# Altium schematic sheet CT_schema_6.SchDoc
size 308 x 321 mm
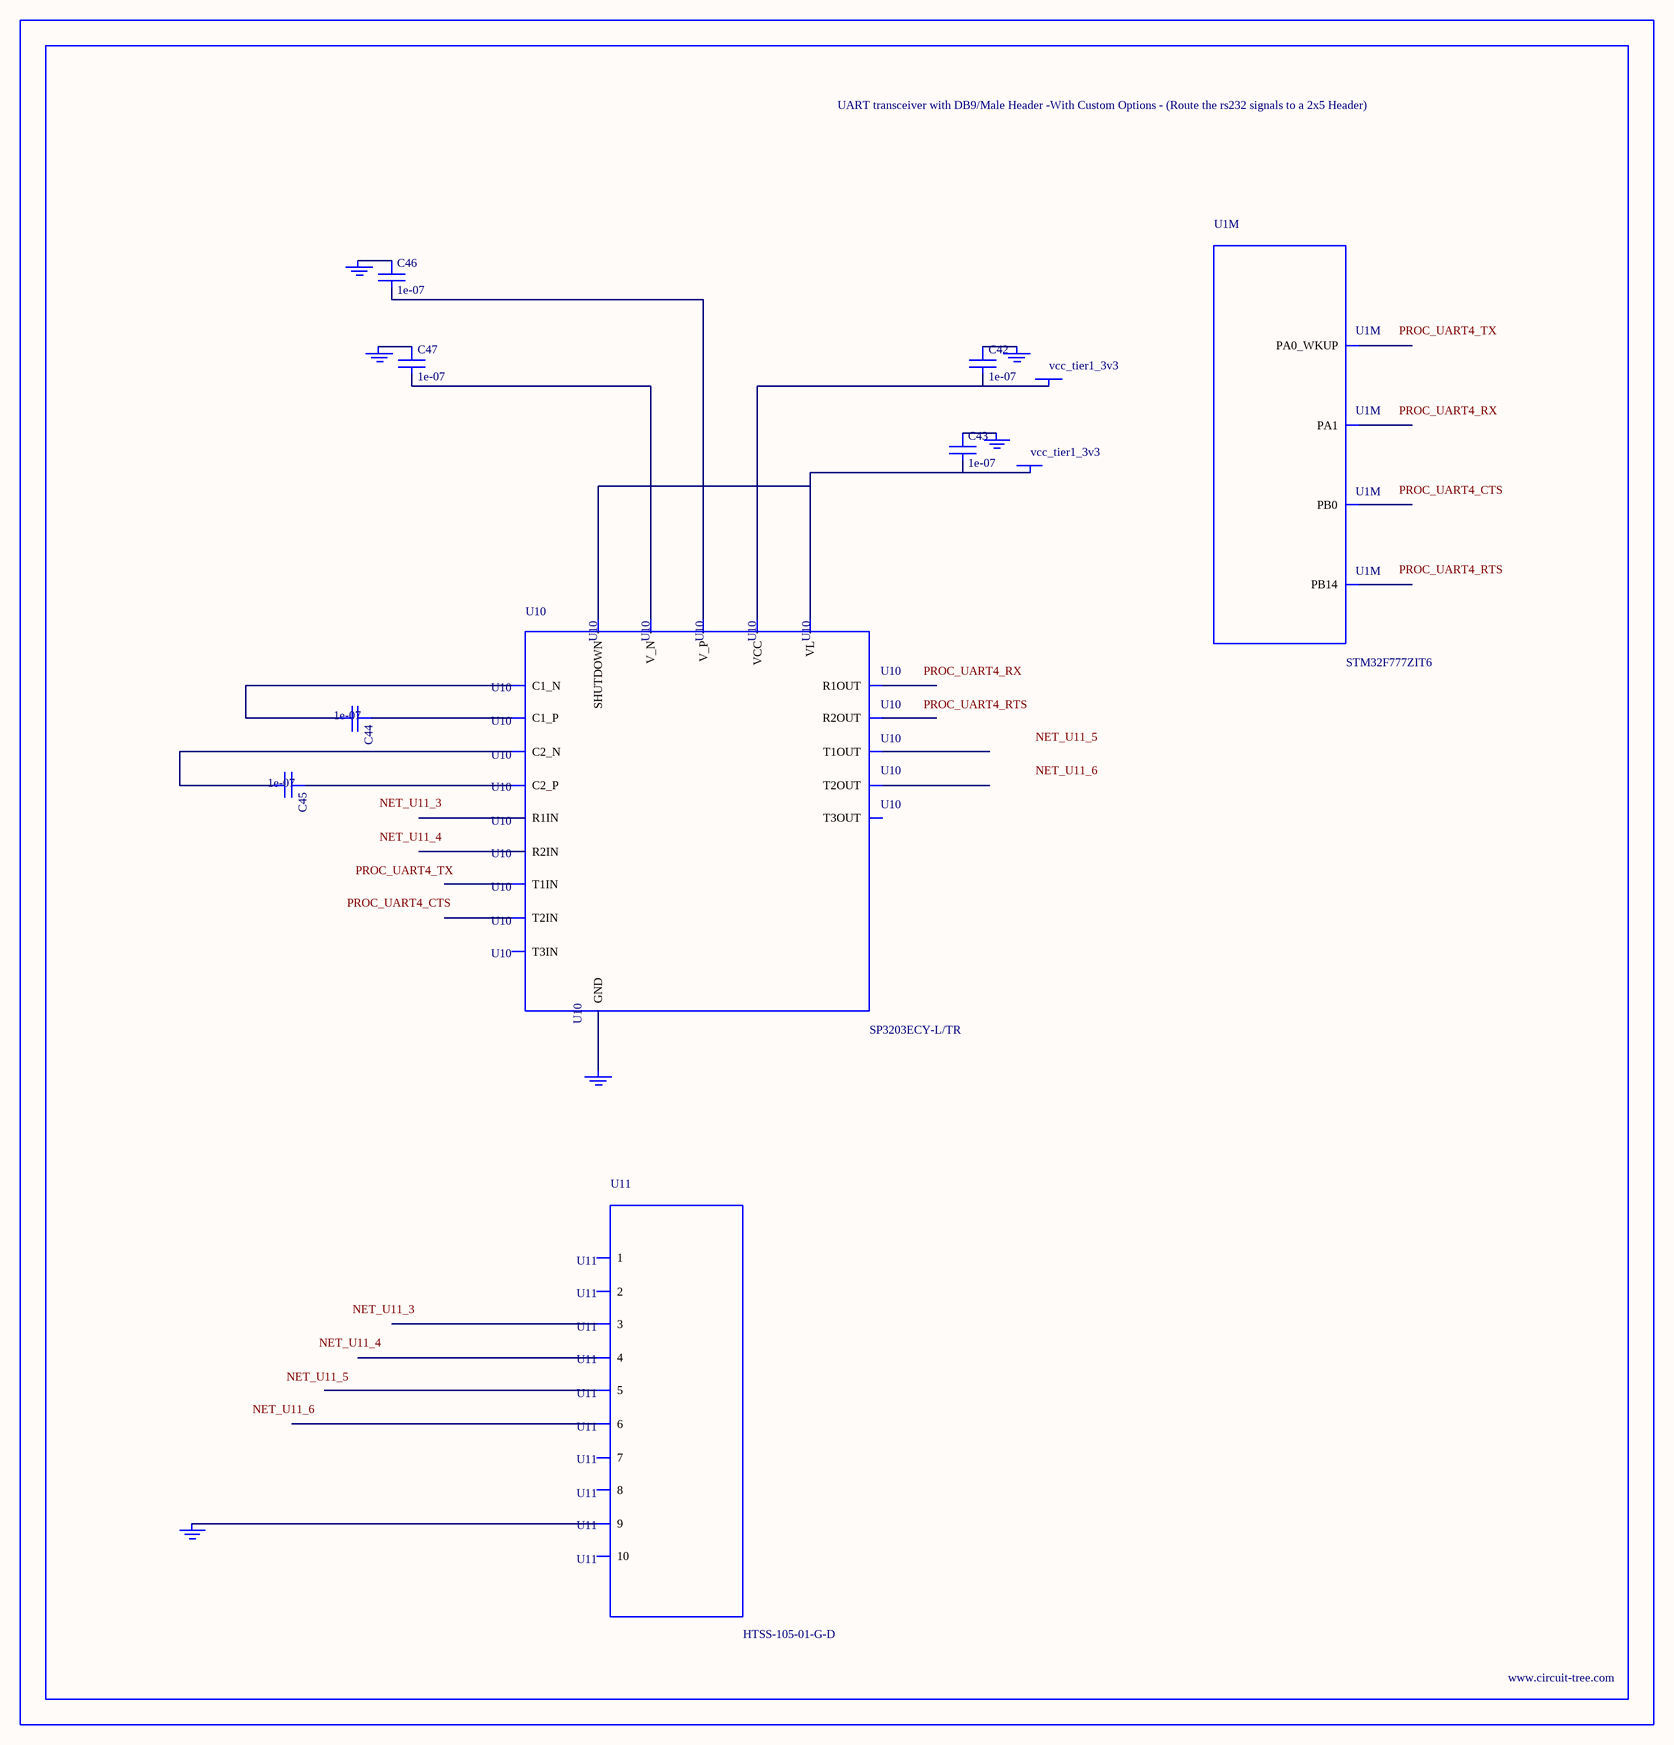
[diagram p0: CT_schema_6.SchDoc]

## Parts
BORDER5  (no value)
C42  1e-07  [C0402]
C43  1e-07  [C0402]
C44  1e-07  [C0402]
C45  1e-07  [C0402]
C46  1e-07  [C0402]
C47  1e-07  [C0402]
GND_INSTANCE_5_0  (no value)
GND_INSTANCE_5_1  (no value)
GND_INSTANCE_5_2  (no value)
GND_INSTANCE_5_3  (no value)
GND_INSTANCE_5_4  (no value)
GND_INSTANCE_5_5  (no value)
POWER_INSTANCE_5_0  vcc_tier1_3v3
POWER_INSTANCE_5_1  vcc_tier1_3v3
U1  STM32F777ZIT6  [LQFP144]  (part M of 13)
U10  SP3203ECY-L/TR  [TSSOP20-I]
U11  HTSS-105-01-G-D  [HTSS-105-01-G-D]

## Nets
NetC42_1: C42.1 GND_INSTANCE_5_3.0(GND)
NetC42_2: C42.2 POWER_INSTANCE_5_1.0(PWR) U10.19(VCC)
NetC43_1: C43.1 GND_INSTANCE_5_2.0(GND)
NetC43_2: C43.2 POWER_INSTANCE_5_0.0(PWR) U10.12(VL) U10.20(SHUTDOWN)
NetC44_1: C44.1 U10.1(C1_P)
NetC44_2: C44.2 U10.3(C1_N)
NetC45_1: C45.1 U10.4(C2_P)
NetC45_2: C45.2 U10.5(C2_N)
NetC46_1: C46.1 GND_INSTANCE_5_0.0(GND)
NetC46_2: C46.2 U10.2(V_P)
NetC47_1: C47.1 GND_INSTANCE_5_1.0(GND)
NetC47_2: C47.2 U10.6(V_N)
NetGND_INSTANCE_5_4_0: GND_INSTANCE_5_4.0(GND) U10.18(GND)
NetGND_INSTANCE_5_5_0: GND_INSTANCE_5_5.0(GND) U11.9

Not connected (* = marked no-connect by the designer): U1 34(PA0_WKUP) 35(PA1) 46(PB0) 75(PB14); U10 7(T1IN) 8(T2IN) 9(T3IN) 10(R2OUT) 11(R1OUT) 13(R2IN) 14(R1IN) 15(T3OUT) 16(T2OUT) 17(T1OUT); U11 1 2 3 4 5 6 7 8 10

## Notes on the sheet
- Labels drawn without touching a wire or pin: NET_U11_3, NET_U11_4, NET_U11_5, NET_U11_6, PROC_UART4_CTS, PROC_UART4_RTS, PROC_UART4_RX, PROC_UART4_TX

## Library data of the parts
BORDER5 = BORDER_PAGE5
C42-C47 = C0402C104K3RACTU
GND_INSTANCE_5_0-GND_INSTANCE_5_5 = GND
POWER_INSTANCE_5_0 POWER_INSTANCE_5_1 = PWR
